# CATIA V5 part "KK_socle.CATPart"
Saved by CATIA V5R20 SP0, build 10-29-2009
Part number: socle
Bounding box of the stored display mesh (mm): x -1211 to 89, y -50 to 10, z -342 to 48
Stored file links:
  G:\Khaled_CFAO_2011\ST2M\ST2M_GR2\tcorbin\Khaled\CAD_ThinkMOTION\KK_socle.CATPart
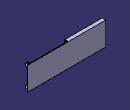
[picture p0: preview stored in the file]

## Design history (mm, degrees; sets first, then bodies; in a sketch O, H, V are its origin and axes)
Set1
  Extract1: ExtractElem edge [face of Pocket1 from Sketch5.L3 | end face of Pocket1]
  Extract2: ExtractElem edge [face of Pocket2 from Sketch6.L1 | end face of Pocket2]
Body1 (main body)
  Sketch1 on zx-plane, origin (0, 0, 0), H (-1, 0, 0), V (0, 0, 1)
    line L1 (-89, 48) -> (1211, 48)
    line L2 (1211, 48) -> (1211, -342)
    line L3 (1211, -342) -> (-89, -342)
    line L4 (-89, -342) -> (-89, 48)
    length L1 = 1300
    length L2 = 390
    horizontal: L1 H, L3 H
    vertical: L2 V, L4 V
  Pad1: profile Sketch1, direction (0, 1, 0), length 10
  Sketch2 on start face of Pad1, origin (0, 0, 0), H (1, 0, 0), V (0, 0, 1)
    line L1 (31.8062, -282) -> (66.8062, -282)
    line L2 (66.8062, -282) -> (66.8062, -332)
    line L3 (66.8062, -332) -> (31.8062, -332)
    line L4 (31.8062, -332) -> (31.8062, -282)
    point P5 (31.8062, 38)
    line L5 (31.8062, 38) -> (66.8062, 38)
    line L6 (66.8062, 38) -> (66.8062, -12)
    line L7 (66.8062, -12) -> (31.8062, -12)
    line L8 (31.8062, -12) -> (31.8062, 38)
    point P7 (66.8062, -12)
    line L9 (-1211, 48) -> (-591.9331, 48)
    line L10 (-591.9331, 48) -> (-591.9331, -12)
    line L11 (-591.9331, -12) -> (-1211, -12)
    line L12 (-1211, -12) -> (-1211, 48)
    line L13 (-1211, -282) -> (-583.0669, -282)
    line L14 (-583.0669, -282) -> (-583.0669, -342)
    line L15 (-583.0669, -342) -> (-1211, -342)
    line L16 (-1211, -342) -> (-1211, -282)
    reference projected line E1 (-1211, 48) -> (89, 48) from edge [start face of Pad1 | face of Pad1 from Sketch1.L1]
    reference projected line E2 (89, -342) -> (-1211, -342) from edge [start face of Pad1 | face of Pad1 from Sketch1.L3]
    reference projected line E3 (-1211, -342) -> (-1211, 48) from edge [start face of Pad1 | face of Pad1 from Sketch1.L2]
    reference projected line E4 (-1211, -342) -> (-1211, 48) from edge [start face of Pad1 | face of Pad1 from Sketch1.L2]
    reference projected line E5 (-1211, 48) -> (89, 48) from edge [start face of Pad1 | face of Pad1 from Sketch1.L1]
    reference projected line E6 (89, -342) -> (-1211, -342) from edge [start face of Pad1 | face of Pad1 from Sketch1.L3]
    length L8 = 50
    length L4 = 50
    length L5 = 35
    length L10 = 60
    length L14 = 60
    distance L5 E5 = 10
    distance L3 E6 = 10
    horizontal: L1 H, L3 H, L5 H, L7 H, L9 H, L11 H, L13 H, L15 H
    vertical: L2 V, L4 V, L6 V, L8 V, L10 V, L12 V, L14 V, L16 V
    coincidence: P5 L4, P7 L2, L9 E1, L15 E2, L12 E3, L16 E4
  Pad2: profile Sketch2, direction (0, -1, 0), length 50
  Sketch3 on face of Pad2 from Sketch2.L7, origin (66.5317, -31.3076, -12), H (1, 0, 0), V (0, -1, 0)
    point P1 (-17.2254, -6.3076)
    reference projected line E1 (0.2746, -31.3076) -> (0.2746, 18.6924) from edge [face of Pad2 from Sketch2.L6 | face of Pad2 from Sketch2.L7]
    reference projected line E2 (-34.7254, 18.6924) -> (0.2746, 18.6924) from edge [face of Pad2 from Sketch2.L7 | end face of Pad2]
    distance E1 P1 = 17.5
    distance E2 P1 = 25
  Hole1: placed by Sketch3, at (49.3062, -25, -12) direction (0, 0, 1), diameter 30, through (limit type 6)
  Sketch4 on face of Pad2 from Sketch2.L3, origin (69.0086, -32.6969, -332), H (1, 0, 0), V (0, -1, 0)
    point P1 (-19.7023, -7.6969)
    reference projected line E1 (-2.2023, -32.6969) -> (-2.2023, 17.3031) from edge [face of Pad2 from Sketch2.L2 | face of Pad2 from Sketch2.L3]
    reference projected line E2 (-37.2023, 17.3031) -> (-2.2023, 17.3031) from edge [face of Pad2 from Sketch2.L3 | end face of Pad2]
    distance P1 E1 = 17.5
    distance P1 E2 = 25
  Hole2: placed by Sketch4, at (49.3062, -25, -332) direction (0, 0, 1), diameter 30, through (limit type 6)
  Sketch5 on face of Pad2 from Sketch2.L11, origin (0, 0, -12), H (1, 0, 0), V (0, -1, 0)
    line L1 (-1211, 40) -> (-591.9331, 40)
    line L2 (-591.9331, 40) -> (-591.9331, 10)
    line L3 (-591.9331, 10) -> (-1211, 10)
    line L4 (-1211, 10) -> (-1211, 40)
    reference projected line E1 (-1211, 0) -> (-1211, 50) from edge [face of Pad2 from Sketch2.L11 | face of Pad2]
    reference projected line E2 (-591.9331, 0) -> (-591.9331, 50) from edge [face of Pad2 from Sketch2.L10 | face of Pad2 from Sketch2.L11]
    reference projected line E3 (-1211, 50) -> (-591.9331, 50) from edge [face of Pad2 from Sketch2.L11 | end face of Pad2]
    length L4 = 30
    distance L1 E3 = 10
    horizontal: L1 H, L3 H
    vertical: L2 V, L4 V
    coincidence: L4 E1, L2 E2
  Pocket1: profile Sketch5, direction (0, 0, 1), length 50
  Sketch6 on face of Pad2 from Sketch2.L13, origin (0, 0, -282), H (1, 0, 0), V (0, 1, 0)
    line L1 (-1211, -10) -> (-583.0669, -10)
    line L2 (-583.0669, -10) -> (-583.0669, -40)
    line L3 (-583.0669, -40) -> (-1211, -40)
    line L4 (-1211, -40) -> (-1211, -10)
    reference projected line E1 (-583.0669, 0) -> (-583.0669, -50) from edge [face of Pad2 from Sketch2.L13 | face of Pad2 from Sketch2.L14]
    reference projected line E2 (-1211, 0) -> (-1211, -50) from edge [face of Pad2 | face of Pad2 from Sketch2.L13]
    reference projected line E3 (-583.0669, -50) -> (-1211, -50) from edge [face of Pad2 from Sketch2.L13 | end face of Pad2]
    length L4 = 30
    distance E3 L3 = 10
    horizontal: L1 H, L3 H
    vertical: L2 V, L4 V
    coincidence: L2 E1, L4 E2
  Pocket2: profile Sketch6, direction (0, 0, -1), length 50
